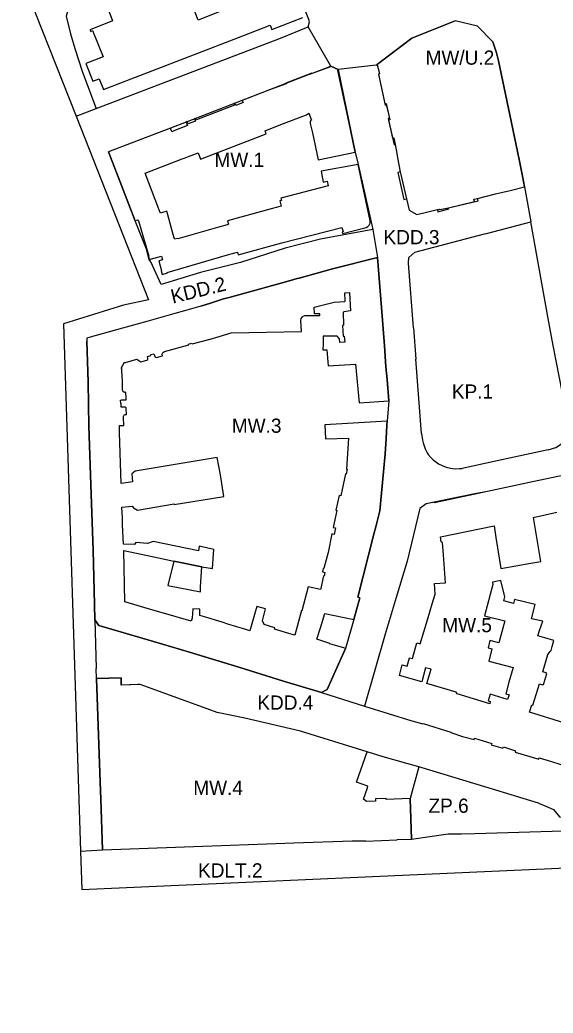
# Model space of a CAD drawing. Extents: x 7424719 to 7426158, y 5545504 to 5546892.
# Drawn here: x 7424952.8 to 7425140.3, y 5545909.5 to 5546259.1 of the extents above; entities that cross this region are included whole.
import ezdxf

# ---------------------------------------------------------------- set-up
doc = ezdxf.new("R2010")
doc.units = 0
for name, color, linetype in [('Linia Zabudowy Nieprzekraczalna', 7, 'Continuous'), ('Linia Zabudowy Obowiązujaca', 7, 'Continuous'), ('Linie Rozgraniczajace', 7, 'Continuous'), ('Oznaczenia Przeznaczenia', 7, 'Continuous')]:
    doc.layers.add(name, color=color, linetype=linetype)

msp = doc.modelspace()

# ---------------------------------------------------------------- linework, layer by layer
at = {"layer": 'Linia Zabudowy Nieprzekraczalna'}
for points in [[(7425120.07, 5546197.81), (7425120.08, 5546197.81), (7425125.18, 5546199.05), (7425130.21, 5546200.29), (7425129.51, 5546204.1), (7425128.36, 5546209.97), (7425125.09, 5546225.67), (7425121.05, 5546244.67), (7425120.39, 5546247.51), (7425119.15, 5546251.34), (7425113.72, 5546256.86), (7425105.81, 5546258.68), (7425090.59, 5546252.67), (7425078.42, 5546243.36)], [(7425051.45, 5546008.77), (7425031.88, 5546013.33), (7425022.18, 5546015.32), (7425010.96, 5546019.38), (7424995.08, 5546025.2), (7424994.3, 5546025.17), (7424988.48, 5546024.95), (7424988.42, 5546027.47), (7424979.78, 5546027.23)]]:
    msp.add_lwpolyline(points, dxfattribs=at)
msp.add_lwpolyline([(7425006.94, 5546068.58), (7425004.83, 5546060.03), (7425016.31, 5546057.77), (7425016.37, 5546059.51), (7425016.8, 5546066.53)], close=True, dxfattribs=at)
at = {"layer": 'Linia Zabudowy Obowiązujaca'}
for points in [[(7425025.8, 5546263.03), (7425015.5, 5546258.94), (7425010.39, 5546272.32)], [(7424983.53, 5546263.81), (7424985.43, 5546258.75), (7424977.52, 5546255.54), (7424977.6, 5546254.99), (7424978.41, 5546255.31), (7424982.07, 5546246.01), (7424976, 5546243.69), (7424978.42, 5546237.47), (7424980.69, 5546238.37), (7424982.22, 5546234.51), (7425029.68, 5546252.87), (7425040.85, 5546257.26), (7425041.44, 5546255.66), (7425052.33, 5546259.88)], [(7425078.42, 5546243.36), (7425078.47, 5546243.19), (7425079.3, 5546240.16), (7425079.31, 5546240.14), (7425079.31, 5546240.14), (7425079.31, 5546240.12), (7425078.92, 5546240.02), (7425081.17, 5546229.56), (7425081.3, 5546229.58), (7425081.55, 5546229.62), (7425082.85, 5546223.91), (7425082.48, 5546223.76), (7425083.86, 5546217.49), (7425084.28, 5546217.57), (7425084.78, 5546215.16), (7425085.34, 5546212.09), (7425085.62, 5546210.48), (7425086.53, 5546205.55), (7425088.75, 5546196.12), (7425089.64, 5546192.06), (7425092.41, 5546190.52), (7425099.6, 5546192.32), (7425100.4, 5546192.48), (7425100.46, 5546192.32), (7425103.57, 5546192.93), (7425112.62, 5546195.1), (7425112.41, 5546195.94), (7425113.73, 5546196.26), (7425120.07, 5546197.81)], [(7425144.15, 5546098.87), (7425131.36, 5546096.16), (7425123.84, 5546094.52), (7425117.27, 5546093.11), (7425098.61, 5546089.16), (7425098.59, 5546089.35), (7425095.72, 5546088.77), (7425093.41, 5546087.14), (7425089.02, 5546068.57), (7425085.17, 5546055.83), (7425081.29, 5546042.88), (7425073.93, 5546017.55), (7425090.63, 5546012.37), (7425094.52, 5546011.29), (7425094.56, 5546011.43), (7425104.38, 5546008.45), (7425104.32, 5546008.31), (7425108.5, 5546006.91), (7425112.49, 5546005.76), (7425112.64, 5546006.23), (7425118.72, 5546004.38), (7425118.55, 5546003.91), (7425122.65, 5546002.72), (7425122.81, 5546003.23), (7425127.12, 5546001.88), (7425126.97, 5546001.4), (7425135.28, 5545998.91), (7425135.44, 5545999.35), (7425139.68, 5545998.02), (7425157.34, 5545992.49)], [(7425144.05, 5546011.68), (7425132.05, 5546015.47), (7425132.79, 5546018.01), (7425133.21, 5546017.85), (7425135.49, 5546025.4), (7425136.66, 5546025.07), (7425136.93, 5546025.2), (7425138.05, 5546028.98), (7425137.91, 5546029.26), (7425136.66, 5546029.65), (7425138.44, 5546035.69), (7425139.26, 5546036.73), (7425139.62, 5546037.16), (7425139.97, 5546038.49), (7425140.58, 5546040.7), (7425137.38, 5546041.63), (7425134.95, 5546042.3), (7425135.55, 5546044.15), (7425136.63, 5546047.47), (7425132.68, 5546048.28), (7425133.96, 5546053.29), (7425126.77, 5546055.12), (7425126.36, 5546053.68), (7425122.96, 5546054.57), (7425123.31, 5546055.99), (7425121.9, 5546061.8), (7425118.99, 5546061.19), (7425119.11, 5546060.31), (7425116.16, 5546049.31), (7425123.27, 5546047.62), (7425121.27, 5546039.89), (7425118.08, 5546040.68), (7425117.42, 5546038.07), (7425118.8, 5546037.72), (7425117.7, 5546033.35), (7425126.28, 5546031.17), (7425124.75, 5546025.95), (7425123.68, 5546021.92), (7425124.86, 5546021.58), (7425124.31, 5546019.9), (7425118.18, 5546021.8), (7425117.45, 5546019.41), (7425118.2, 5546019.22), (7425118.01, 5546018.37), (7425112.32, 5546020.07), (7425106.51, 5546021.86), (7425106.19, 5546022.43), (7425095.92, 5546025.54), (7425097.43, 5546030.52), (7425095.42, 5546031.08), (7425094.14, 5546026.07), (7425086.33, 5546028.3), (7425087.27, 5546032.09), (7425088.98, 5546031.63), (7425089.86, 5546034.55), (7425090.84, 5546034.32), (7425092.34, 5546039.87), (7425093.61, 5546039.53), (7425096.1, 5546047.88), (7425097.8, 5546053.6), (7425098.8, 5546056.96), (7425098.58, 5546060.7), (7425102.52, 5546060.94), (7425101.77, 5546070.75), (7425101.37, 5546075.13), (7425100.98, 5546075.39), (7425100.7, 5546077.1), (7425119.54, 5546080.99), (7425120.2, 5546076.89), (7425121.9, 5546066.01), (7425132.45, 5546067.84), (7425135.96, 5546068.46), (7425133.37, 5546083.97), (7425133.76, 5546084.04), (7425136.02, 5546084.57), (7425141.61, 5546085.83)], [(7424979.78, 5546027.23), (7424981.03, 5545990.79), (7424981.28, 5545984.79), (7424981.93, 5545966.93), (7425023.61, 5545968.55), (7425049.12, 5545969.45), (7425069.68, 5545970.17), (7425074.4, 5545970.21), (7425074.41, 5545970.04), (7425085.51, 5545970.45), (7425085.52, 5545970.6), (7425090.56, 5545970.77), (7425090.08, 5545985.02), (7425081.61, 5545984.68), (7425081.56, 5545985.1), (7425077.81, 5545984.91), (7425077.8, 5545984.12), (7425074.72, 5545983.97), (7425073.69, 5545984.83), (7425075, 5545988.8), (7425075.19, 5545989.37), (7425071.15, 5545990.82), (7425074.9, 5546001.46), (7425051.45, 5546008.77)]]:
    msp.add_lwpolyline(points, dxfattribs=at)
for points in [[(7425002.22, 5546191.1), (7425001.72, 5546192.42), (7424996.86, 5546205.17), (7425009.89, 5546210.12), (7425010.55, 5546210.38), (7425015.48, 5546212.23), (7425016.36, 5546210.02), (7425039.39, 5546219), (7425039.07, 5546219.99), (7425044.54, 5546222.27), (7425053.55, 5546225.64), (7425053.99, 5546225.87), (7425054.36, 5546226.25), (7425055.31, 5546223.83), (7425055.21, 5546223.74), (7425055.12, 5546223.64), (7425055.04, 5546223.53), (7425054.98, 5546223.41), (7425054.93, 5546223.28), (7425054.89, 5546223.15), (7425054.87, 5546223.01), (7425054.86, 5546222.88), (7425054.87, 5546222.74), (7425054.9, 5546222.61), (7425055.72, 5546219.29), (7425057.7, 5546209.85), (7425070.76, 5546212.52), (7425068.46, 5546223.36), (7425064.58, 5546241.22), (7425064.74, 5546241.59), (7425062.11, 5546242.83), (7425062, 5546242.54), (7425055.55, 5546240.14), (7425055.46, 5546240.28), (7425046.38, 5546236.74), (7425046.39, 5546236.56), (7425039.99, 5546234.25), (7425031.01, 5546230.75), (7425031.3, 5546229.97), (7425028.72, 5546228.97), (7425028.41, 5546229.73), (7425028.1, 5546229.61), (7425028.27, 5546229.06), (7425014.93, 5546223.84), (7425014.66, 5546224.39), (7425014.38, 5546224.28), (7425014.23, 5546224.23), (7425014.53, 5546223.44), (7425012.02, 5546222.43), (7425011.69, 5546223.25), (7425011.27, 5546223.09), (7425011.74, 5546221.88), (7425006.97, 5546219.97), (7425006.23, 5546219.7), (7425005.74, 5546220.93), (7424983.98, 5546212.59), (7424993.1, 5546188.92), (7424993.3, 5546188.42), (7424994.23, 5546188.75), (7424994.38, 5546188.29), (7424994.49, 5546188.33), (7424998.12, 5546175.91), (7424998, 5546175.89), (7424998.29, 5546174.73), (7425001.35, 5546175.61), (7425002.6, 5546175.97), (7425002.95, 5546174.63), (7425001.71, 5546174.24), (7425002.64, 5546170.74), (7425002.52, 5546170.7), (7425002.84, 5546169.5), (7425004.67, 5546170.02), (7425004.66, 5546170.17), (7425024.96, 5546176.14), (7425028.43, 5546177.04), (7425029.3, 5546177.29), (7425029.6, 5546176.34), (7425044.92, 5546180.62), (7425066.07, 5546186.05), (7425066.46, 5546184.59), (7425066.17, 5546184.51), (7425066.32, 5546183.87), (7425074.53, 5546185.97), (7425075.2, 5546186.3), (7425075.65, 5546186.77), (7425075.96, 5546187.53), (7425075.95, 5546188.33), (7425071.72, 5546208.12), (7425058.75, 5546205.84), (7425059.51, 5546201.97), (7425060.82, 5546202.31), (7425061.25, 5546200.61), (7425044.54, 5546196.32), (7425044.75, 5546195.48), (7425044.2, 5546195.34), (7425044.66, 5546193.48), (7425041.19, 5546192.55), (7425025.82, 5546188.33), (7425026.19, 5546187.15), (7425025.71, 5546186.99), (7425022.27, 5546186.03), (7425008.36, 5546182.04), (7425008.33, 5546182.16), (7425007.27, 5546181.88), (7425007.17, 5546182.24), (7425007.06, 5546182.21), (7425004.45, 5546191.71)], [(7425003.71, 5546142.34), (7425012.19, 5546144.69), (7425012.11, 5546144.96), (7425013.28, 5546145.28), (7425013.35, 5546145.01), (7425019.69, 5546146.76), (7425022.91, 5546147.68), (7425027.14, 5546148.89), (7425051.84, 5546149.37), (7425051.66, 5546153.29), (7425051.74, 5546153.97), (7425052.04, 5546154.5), (7425052.48, 5546154.8), (7425052.98, 5546155.02), (7425058.3, 5546155.07), (7425058.29, 5546155.65), (7425056.39, 5546155.67), (7425056.35, 5546157.98), (7425063.28, 5546159.78), (7425067.05, 5546159.98), (7425067.17, 5546160.14), (7425067.13, 5546163), (7425068.69, 5546163.09), (7425068.96, 5546158.67), (7425069.08, 5546156.67), (7425066.68, 5546156.37), (7425066.48, 5546156.09), (7425066.63, 5546151.6), (7425066.31, 5546151.52), (7425066.54, 5546147.76), (7425066.83, 5546147.78), (7425067.04, 5546145.62), (7425065.29, 5546145.54), (7425065.24, 5546146.85), (7425064.41, 5546147.72), (7425059.46, 5546147.75), (7425059.41, 5546145.04), (7425059.37, 5546142.89), (7425060.79, 5546142.97), (7425061.23, 5546137.37), (7425070.82, 5546137.85), (7425072.09, 5546124.24), (7425082.52, 5546124.95), (7425081.93, 5546132.48), (7425081.53, 5546137.01), (7425081, 5546144.37), (7425079.94, 5546157.82), (7425078.59, 5546175.4), (7425062.71, 5546171.47), (7425050.97, 5546168.19), (7425050.33, 5546168.01), (7425048, 5546167.38), (7425045.02, 5546166.56), (7425026.37, 5546161.38), (7425024.44, 5546160.86), (7425019.82, 5546159.33), (7425016.42, 5546158.28), (7425010.65, 5546156.64), (7425007.25, 5546155.69), (7424997.41, 5546152.93), (7424994.1, 5546152.01), (7424988.89, 5546150.54), (7424977.59, 5546147.44), (7424976.39, 5546147.11), (7424976.35, 5546145.99), (7424976.85, 5546131.62), (7424977.11, 5546116.06), (7424977.86, 5546092.12), (7424978.59, 5546072.37), (7424978.94, 5546058.4), (7424979.21, 5546047.96), (7424980.57, 5546045.89), (7424999.76, 5546040.27), (7425012.43, 5546036.53), (7425029.86, 5546031.25), (7425045.55, 5546026.32), (7425058.9, 5546022.41), (7425060.86, 5546023.37), (7425067.28, 5546037.85), (7425066.71, 5546038.03), (7425063.83, 5546038.88), (7425061.75, 5546039.5), (7425061.79, 5546039.64), (7425057.22, 5546041.13), (7425058.48, 5546045.08), (7425060.04, 5546050.14), (7425070.23, 5546048.05), (7425072.3, 5546055.72), (7425071.68, 5546055.85), (7425077.26, 5546078.05), (7425078.1, 5546081.09), (7425079.36, 5546086.32), (7425080.64, 5546100.03), (7425081.21, 5546106.37), (7425081.58, 5546111.63), (7425081.86, 5546116.48), (7425081.94, 5546117.9), (7425060.08, 5546116.54), (7425060.32, 5546111.59), (7425068.33, 5546111.82), (7425067.63, 5546100.99), (7425067.89, 5546100.98), (7425067.5, 5546099.2), (7425067.25, 5546099.26), (7425065.61, 5546091.59), (7425065.03, 5546091.72), (7425063.96, 5546086.55), (7425064.26, 5546086.36), (7425062.99, 5546080.48), (7425063.84, 5546080.33), (7425063.36, 5546077.98), (7425062.49, 5546078.15), (7425061.19, 5546071.66), (7425059.81, 5546066.42), (7425059.74, 5546065.95), (7425059.43, 5546066), (7425059.24, 5546064.81), (7425060.03, 5546064.63), (7425059.83, 5546063.33), (7425059.54, 5546063.38), (7425059.44, 5546062.91), (7425058.6, 5546059.01), (7425058.52, 5546058.63), (7425054.2, 5546059.54), (7425052, 5546051.11), (7425051.84, 5546051.18), (7425050.75, 5546047.32), (7425049.49, 5546042.52), (7425049.01, 5546042.66), (7425047.38, 5546043.15), (7425042.36, 5546044.66), (7425042.51, 5546045.15), (7425038.76, 5546046.32), (7425038.08, 5546047.6), (7425039.21, 5546051.76), (7425036.18, 5546052.65), (7425035.34, 5546049.79), (7425033.66, 5546044.1), (7425032.26, 5546044.55), (7425025.96, 5546046.43), (7425023.94, 5546047.05), (7425017.78, 5546048.99), (7425016.05, 5546049.47), (7425016.1, 5546051.64), (7425013.6, 5546051.77), (7425013.37, 5546048.49), (7425013.08, 5546047.43), (7425002.45, 5546050.54), (7424999.61, 5546051.36), (7424989.74, 5546054.22), (7424989.38, 5546072.3), (7425001.6, 5546069.7), (7425006.94, 5546068.58), (7425016.8, 5546066.53), (7425020.5, 5546065.95), (7425020.95, 5546071.15), (7425021.06, 5546072.73), (7425015.85, 5546073.84), (7425015.62, 5546072.24), (7424999.72, 5546075.46), (7424997.75, 5546074.76), (7424993.65, 5546075.2), (7424993.13, 5546074.43), (7424989.2, 5546074.55), (7424988.95, 5546081.41), (7424988.87, 5546083.72), (7424988.73, 5546087.61), (7424992.36, 5546087.93), (7424992.76, 5546087.38), (7424994.13, 5546086.54), (7425007.06, 5546088.77), (7425007.09, 5546088.57), (7425024.51, 5546091.36), (7425023.32, 5546099), (7425022.21, 5546105.1), (7424993.41, 5546100.29), (7424992.2, 5546099.31), (7424992.48, 5546096.55), (7424991.7, 5546096.43), (7424988.48, 5546095.92), (7424987.88, 5546113.8), (7424987.8, 5546115.99), (7424987.8, 5546116.31), (7424989.32, 5546116.34), (7424989.2, 5546119.15), (7424989.2, 5546119.33), (7424989.23, 5546119.5), (7424989.29, 5546119.66), (7424989.38, 5546119.81), (7424989.5, 5546119.95), (7424989.63, 5546120.06), (7424989.79, 5546120.15), (7424989.95, 5546120.2), (7424990.12, 5546120.23), (7424990.3, 5546120.23), (7424990.24, 5546122.28), (7424990.23, 5546122.35), (7424990.21, 5546122.43), (7424990.18, 5546122.5), (7424990.18, 5546122.5), (7424990.14, 5546122.56), (7424990.1, 5546122.62), (7424990.04, 5546122.67), (7424989.98, 5546122.71), (7424989.91, 5546122.74), (7424989.83, 5546122.76), (7424989.76, 5546122.77), (7424988.44, 5546122.75), (7424988.42, 5546123.95), (7424988.42, 5546124.05), (7424988.3, 5546124.05), (7424988.26, 5546125.23), (7424988.38, 5546125.23), (7424988.38, 5546125.31), (7424990.15, 5546125.36), (7424990.14, 5546125.93), (7424990.08, 5546127.92), (7424989.91, 5546127.92), (7424989.74, 5546127.94), (7424989.57, 5546128), (7424989.42, 5546128.07), (7424989.28, 5546128.18), (7424989.16, 5546128.3), (7424989.06, 5546128.44), (7424988.98, 5546128.59), (7424988.93, 5546128.76), (7424988.91, 5546128.93), (7424988.9, 5546131.8), (7424988.68, 5546135.62), (7424988.66, 5546136.17), (7424988.76, 5546136.35), (7424988.43, 5546136.53), (7424989.62, 5546138.62), (7424989.95, 5546138.43), (7424990.01, 5546138.54), (7424993.94, 5546139.63), (7424995.41, 5546138.71), (7424997.51, 5546139.29), (7424997.79, 5546139.54), (7424997.85, 5546139.91), (7424997.66, 5546140.66), (7424998.9, 5546141), (7424998.83, 5546141.26), (7424999.96, 5546141.58), (7425000.03, 5546141.32), (7425000.09, 5546141.33), (7425000.29, 5546140.59), (7425000.55, 5546140.33), (7425000.91, 5546140.24), (7425002.97, 5546140.81), (7425002.9, 5546141.26), (7425003.02, 5546141.73), (7425003.32, 5546142.12)]]:
    msp.add_lwpolyline(points, close=True, dxfattribs=at)
at = {"layer": 'Linie Rozgraniczajace'}
for p, q in [((7425062.11, 5546242.83), (7425054.2, 5546256.63)), ((7425113.72, 5546256.86), (7425105.81, 5546258.68)), ((7425119.15, 5546251.34), (7425113.72, 5546256.86)), ((7425054.77, 5546240.02), (7425062.11, 5546242.83)), ((7425078.1, 5546243.11), (7425064.74, 5546241.59)), ((7425091.66, 5546177.3), (7425089.61, 5546175.42)), ((7425091.24, 5546150.72), (7425092.02, 5546139.65)), ((7424976.39, 5546147.11), (7424976.35, 5546145.99)), ((7425072.3, 5546055.72), (7425071.68, 5546055.85)), ((7424979.21, 5546047.96), (7424979.66, 5546030.85)), ((7424995.08, 5546025.2), (7424988.48, 5546024.95))]:
    msp.add_line(p, q, dxfattribs=at)
for points in [[(7425067.33, 5546367.48), (7425068.8, 5546365.73), (7425074.1, 5546349.89), (7425045.73, 5546327.08), (7425015.41, 5546302.7), (7424971.75, 5546269.52), (7424969.15, 5546260.38), (7424970.61, 5546254.21), (7424972.18, 5546248.99), (7424974.87, 5546240.61), (7424979.68, 5546227.83)], [(7425054.2, 5546256.63), (7425054.62, 5546258.34), (7425054.38, 5546259.25), (7425051.78, 5546266.05), (7425050.52, 5546269.41), (7425047.85, 5546272.19), (7425044.11, 5546277.95), (7425043.52, 5546279.07), (7425043.29, 5546279.76), (7425040.34, 5546287.08), (7425039.35, 5546290.33), (7425038.28, 5546297.38), (7425038.16, 5546300.88), (7425038.51, 5546305.58), (7425041.88, 5546317.19), (7425042.53, 5546319.43), (7425045.73, 5546327.08)], [(7424957.24, 5546278.61), (7424952.83, 5546275.68), (7424958.33, 5546261.26), (7424972.58, 5546225.13), (7424998.07, 5546160.52), (7424989.29, 5546158.65), (7424968.14, 5546152.12), (7424974.15, 5545966.53), (7424974.59, 5545952.99), (7425152.89, 5545960.96), (7425151.54, 5545949.85), (7425136.55, 5545826.39)], [(7424972.58, 5546225.13), (7424979.68, 5546227.83), (7425044.4, 5546252.64), (7425054.2, 5546256.63)], [(7425078.1, 5546243.11), (7425090.59, 5546252.67), (7425105.81, 5546258.68)], [(7425119.15, 5546251.34), (7425120.39, 5546247.51), (7425121.05, 5546244.67), (7425125.09, 5546225.67), (7425128.36, 5546209.97), (7425129.51, 5546204.1), (7425130.21, 5546200.29), (7425132.46, 5546188.04)], [(7425062.11, 5546242.83), (7425064.74, 5546241.59), (7425068.46, 5546223.36), (7425070.76, 5546212.52), (7425071.72, 5546208.12), (7425076.86, 5546185.26)], [(7425078.1, 5546243.11), (7425078.47, 5546243.19), (7425079.3, 5546240.16), (7425079.31, 5546240.12), (7425078.92, 5546240.02), (7425081.28, 5546229.06), (7425081.66, 5546229.15), (7425082.73, 5546224.45), (7425082.35, 5546224.37), (7425084.39, 5546215.09), (7425084.78, 5546215.16), (7425085.34, 5546212.09), (7425085.62, 5546210.48), (7425086.53, 5546205.55), (7425085.65, 5546205.35), (7425087.79, 5546195.89), (7425088.75, 5546196.12), (7425089.64, 5546192.06), (7425092.41, 5546190.52), (7425099.6, 5546192.32), (7425099.74, 5546191.56), (7425103.62, 5546192.6), (7425103.57, 5546192.93), (7425113.97, 5546195.42), (7425113.73, 5546196.26), (7425120.08, 5546197.81), (7425125.18, 5546199.05), (7425130.21, 5546200.29)], [(7425054.77, 5546240.02), (7425039.99, 5546234.25), (7425019.15, 5546226.12), (7425011.27, 5546223.09), (7425005.74, 5546220.93), (7424983.98, 5546212.59)], [(7425076.86, 5546185.26), (7425058.49, 5546181.86), (7425046.07, 5546178.67), (7425030.36, 5546173.65), (7425016.37, 5546170.21), (7425002.45, 5546165.96), (7424998.85, 5546173.96), (7424998.29, 5546174.73), (7424997.37, 5546178.42), (7424993.1, 5546188.92), (7424983.98, 5546212.59)], [(7425091.66, 5546177.3), (7425116.21, 5546183.75), (7425116.93, 5546183.94), (7425132.46, 5546188.04)], [(7425138.58, 5546107.76), (7425141.26, 5546108.56), (7425143.23, 5546109.81), (7425145.37, 5546113.16), (7425145.74, 5546116.86), (7425140.37, 5546144.43), (7425138.59, 5546153.92), (7425132.46, 5546188.04)], [(7425076.86, 5546185.26), (7425078.59, 5546175.4), (7425079.94, 5546157.82), (7425081, 5546144.37), (7425081.53, 5546137.01), (7425081.93, 5546132.48)], [(7425016.42, 5546158.28), (7425019.82, 5546159.33), (7425024.44, 5546160.86), (7425026.37, 5546161.38), (7425045.02, 5546166.56), (7425048, 5546167.38), (7425050.33, 5546168.01), (7425050.97, 5546168.19), (7425062.71, 5546171.47), (7425078.59, 5546175.4)], [(7425091.24, 5546150.72), (7425089.44, 5546173.49), (7425089.61, 5546175.42)], [(7425016.42, 5546158.28), (7425010.65, 5546156.64), (7425007.25, 5546155.69), (7424997.41, 5546152.93), (7424994.1, 5546152.01), (7424988.89, 5546150.54), (7424977.59, 5546147.44), (7424976.39, 5546147.11)], [(7424978.59, 5546072.37), (7424977.86, 5546092.12), (7424977.11, 5546116.06), (7424976.85, 5546131.62), (7424976.35, 5546145.99)], [(7425094.03, 5546113.45), (7425092.02, 5546139.65)], [(7425081.93, 5546132.48), (7425082.52, 5546124.95), (7425081.94, 5546117.9), (7425081.86, 5546116.48), (7425081.58, 5546111.63), (7425081.21, 5546106.37), (7425080.64, 5546100.03), (7425079.36, 5546086.32)], [(7425094.03, 5546113.45), (7425094.4, 5546111.19), (7425094.62, 5546110.17), (7425095.31, 5546108.13), (7425095.99, 5546106.75), (7425096.33, 5546106.12), (7425097.32, 5546105.01), (7425098.18, 5546104.23), (7425098.98, 5546103.6), (7425100.01, 5546102.87), (7425101.25, 5546102.19), (7425102.72, 5546101.64), (7425104.25, 5546101.25), (7425105.84, 5546101.1), (7425107.22, 5546101.15), (7425108.29, 5546101.23)], [(7425138.58, 5546107.76), (7425120.61, 5546103.85), (7425108.29, 5546101.23)], [(7425144.15, 5546098.87), (7425131.36, 5546096.16), (7425123.84, 5546094.52), (7425117.27, 5546093.11), (7425112.77, 5546092.23), (7425095.72, 5546088.77), (7425093.41, 5546087.14), (7425089.02, 5546068.57), (7425085.17, 5546055.83), (7425081.29, 5546042.88), (7425073.93, 5546017.55)], [(7425079.36, 5546086.32), (7425078.1, 5546081.09), (7425077.26, 5546078.05), (7425071.68, 5546055.85)], [(7425029.86, 5546031.25), (7425012.43, 5546036.53), (7424999.76, 5546040.27), (7424980.57, 5546045.89), (7424979.21, 5546047.96), (7424978.94, 5546058.4), (7424978.59, 5546072.37)], [(7425072.3, 5546055.72), (7425070.23, 5546048.05), (7425067.28, 5546037.85), (7425060.86, 5546023.37), (7425058.9, 5546022.41), (7425045.55, 5546026.32), (7425029.86, 5546031.25)], [(7424981.93, 5545966.93), (7424981.28, 5545984.79), (7424981.03, 5545990.79), (7424979.78, 5546027.23), (7424979.66, 5546030.85)], [(7424979.78, 5546027.23), (7424988.42, 5546027.47), (7424988.48, 5546024.95)], [(7425074.9, 5546001.46), (7425051.45, 5546008.77), (7425031.88, 5546013.33), (7425022.18, 5546015.32), (7425010.96, 5546019.38), (7424995.08, 5546025.2)], [(7425058.9, 5546022.41), (7425073.93, 5546017.55), (7425090.63, 5546012.37), (7425094.52, 5546011.29), (7425094.56, 5546011.43), (7425104.38, 5546008.45), (7425104.32, 5546008.31), (7425108.5, 5546006.91), (7425112.49, 5546005.76), (7425112.64, 5546006.23), (7425118.72, 5546004.38), (7425118.55, 5546003.91), (7425122.65, 5546002.72), (7425122.81, 5546003.23), (7425127.12, 5546001.88), (7425126.97, 5546001.4), (7425135.28, 5545998.91), (7425135.44, 5545999.35), (7425139.68, 5545998.02), (7425157.34, 5545992.49), (7425165.41, 5545989.96)], [(7425135.12, 5545983.41), (7425117.47, 5545988.77), (7425093.07, 5545996.19), (7425088.86, 5545997.32), (7425080.5, 5545999.7), (7425074.9, 5546001.46)], [(7425093.07, 5545996.19), (7425090.08, 5545985.02), (7425090.56, 5545970.77)], [(7425135.12, 5545983.41), (7425137.78, 5545982.3), (7425140.43, 5545981.19), (7425142.54, 5545978.61), (7425143.58, 5545978.38), (7425144.62, 5545978.16), (7425147.42, 5545977.12), (7425150.21, 5545976.08), (7425152.4, 5545975.36), (7425153.34, 5545975.05)], [(7425090.56, 5545970.77), (7425103.41, 5545972.61), (7425108.07, 5545972.64), (7425112.72, 5545972.68), (7425128.3, 5545973.16), (7425143.88, 5545973.64), (7425151.79, 5545973.88), (7425153.34, 5545975.05)], [(7424974.15, 5545966.53), (7424981.93, 5545966.93), (7425023.61, 5545968.55), (7425049.12, 5545969.45), (7425069.68, 5545970.17), (7425074.4, 5545970.21), (7425074.41, 5545970.04), (7425085.51, 5545970.45), (7425085.52, 5545970.6), (7425090.56, 5545970.77)]]:
    msp.add_lwpolyline(points, dxfattribs=at)

# ---------------------------------------------------------------- texts
at = {"layer": 'Oznaczenia Przeznaczenia'}
for s, p in [('MW/U.2', (7425095.46, 5546243.29)), ('MW.1', (7425021.24, 5546207.31)), ('KDD.3', (7425080.66, 5546180.11)), ('KP.1', (7425104.7, 5546125.76)), ('MW.3', (7425027.34, 5546113.75)), ('MW.5', (7425101.33, 5546043.57)), ('KDD.4', (7425036.31, 5546016.31)), ('MW.4', (7425013.8, 5545986.34)), ('ZP.6', (7425096.49, 5545980.02)), ('KDLT.2', (7425015.47, 5545957.24))]:
    msp.add_text(s, height=5, dxfattribs=at).set_placement(p)
msp.add_text('KDD.2', height=5, rotation=13.9174, dxfattribs=at).set_placement((7425006.58, 5546159.18))

doc.saveas('drawing.dxf')
